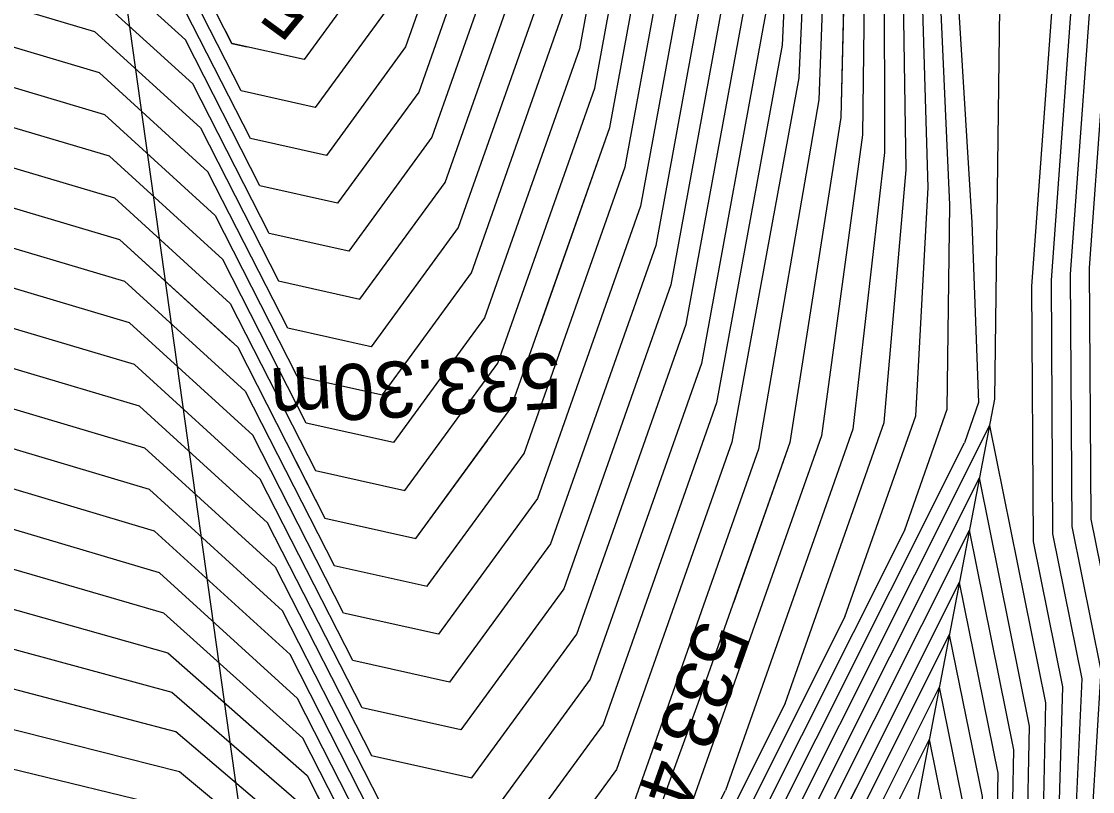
# Model space of a CAD drawing. Extents: x -866683 to -866410, y -1041951 to -1040252.
# Drawn here: x -866454.85 to -866449.11, y -1041936.13 to -1041932.01 of the extents above; entities that cross this region are included whole.
import ezdxf

# ---------------------------------------------------------------- set-up
doc = ezdxf.new("R2010")
doc.units = 0
for name, color, linetype in [('BODY', 7, 'Continuous'), ('BODY_2016', 7, 'Continuous'), ('BREAKLINE', 7, 'Continuous'), ('V-VEDL', 7, 'Continuous'), ('V_po_cm', 7, 'Continuous')]:
    doc.layers.add(name, color=color, linetype=linetype)

msp = doc.modelspace()

# ---------------------------------------------------------------- linework, layer by layer
at = {"layer": 'BREAKLINE'}
for points in [[(-866451.679, -1041950.508), (-866455.618, -1041922.473), (-866456.719, -1041912.396), (-866455.207, -1041909.853), (-866453.752, -1041908.342), (-866450, -1041907.538), (-866447.7, -1041908.076), (-866445.165, -1041909.459), (-866437.422, -1041915.176), (-866426.565, -1041925.108), (-866438.22, -1041915.868), (-866445.312, -1041910.554), (-866447.7, -1041908.076)], [(-866430.202, -1041927.282), (-866445.247, -1041913.64), (-866449.543, -1041926.354), (-866449.641, -1041934.033), (-866450.183, -1041936.864), (-866452.267, -1041937.851), (-866451.576, -1041945.087)]]:
    msp.add_lwpolyline(points, dxfattribs=at)
at = {"layer": 'V-VEDL'}
for points in [[(-866449.6778, -1041924.8534), (-866451.5122, -1041924.6245), (-866452.0867, -1041925.0785), (-866452.3185, -1041926.1012), (-866452.2076, -1041927.6924), (-866452.2736, -1041929.1497), (-866452.5165, -1041930.4732), (-866452.9364, -1041931.6628), (-866453.3395, -1041932.2146), (-866453.7258, -1041932.1285), (-866454.0953, -1041931.4045), (-866454.5968, -1041930.9482), (-866455.2304, -1041930.7597), (-866456.7616, -1041930.9181)], [(-866457.0626, -1041933.1405), (-866455.1284, -1041932.9404), (-866454.3281, -1041933.1785), (-866453.6946, -1041933.7549), (-866453.2278, -1041934.6694), (-866452.7398, -1041934.7782), (-866452.2307, -1041934.0812), (-866451.7003, -1041932.5785), (-866451.3935, -1041930.9067), (-866451.3101, -1041929.0659), (-866451.4503, -1041927.056), (-866451.3268, -1041925.7431), (-866450.9398, -1041925.1272), (-866449.6386, -1041925.2896)], [(-866449.5994, -1041925.7259), (-866450.3673, -1041925.63), (-866450.5669, -1041926.4076), (-866450.582, -1041928.0107), (-866450.4127, -1041930.4394), (-866450.4641, -1041932.5242), (-866450.7364, -1041934.2652), (-866451.2295, -1041935.6623), (-866451.5972, -1041936.6715), (-866451.8395, -1041937.2927), (-866451.9565, -1041937.526), (-866451.8502, -1041937.6044), (-866451.5207, -1041937.5279), (-866450.9679, -1041937.2965), (-866450.586, -1041937.3604), (-866450.3749, -1041937.7197), (-866450.2943, -1041939.0287)], [(-866449.8288, -1041935.014), (-866450.566, -1041936.4847), (-866450.7385, -1041936.9442), (-866450.7148, -1041937.128), (-866450.4951, -1041937.036), (-866450.3432, -1041937.0614), (-866450.2593, -1041937.2042), (-866450.2272, -1041937.7247)], [(-866449.8288, -1041935.014), (-866449.622, -1041936.0349), (-866449.6318, -1041936.5063), (-866449.7548, -1041936.9385), (-866450.2272, -1041937.7247)], [(-866457.3636, -1041935.3629), (-866455.0264, -1041935.1211), (-866454.0691, -1041935.3898), (-866453.3231, -1041936.048), (-866452.7882, -1041937.0959), (-866452.4298, -1041937.7979), (-866452.2476, -1041938.1541), (-866452.2361, -1041938.1747)]]:
    msp.add_lwpolyline(points, dxfattribs=at)
at = {"layer": 'V_po_cm'}
for points in [[(-866448.7617, -1041924.9364), (-866449.2179, -1041924.777), (-866449.4459, -1041924.837), (-866449.8947, -1041924.84), (-866450.5644, -1041924.7859), (-866451.455, -1041924.6747), (-866452.0107, -1041925.145), (-866452.2317, -1041926.1967), (-866452.1179, -1041927.8297), (-866452.1856, -1041929.3254), (-866452.4349, -1041930.6837), (-866452.8658, -1041931.9047), (-866453.2795, -1041932.4709), (-866453.676, -1041932.3826), (-866454.0552, -1041931.6395), (-866454.57, -1041931.1712), (-866455.2202, -1041930.9777)], [(-866448.7851, -1041924.9789), (-866449.2276, -1041924.8242), (-866449.4488, -1041924.8824), (-866449.8842, -1041924.8853), (-866450.5338, -1041924.8328), (-866451.3977, -1041924.725), (-866451.9348, -1041925.2115), (-866452.1449, -1041926.2921), (-866452.0281, -1041927.9671), (-866452.0976, -1041929.5011), (-866452.3533, -1041930.8942), (-866452.7952, -1041932.1465), (-866453.2195, -1041932.7273), (-866453.6262, -1041932.6367), (-866454.0151, -1041931.8745), (-866454.5431, -1041931.3943), (-866455.21, -1041931.1958)], [(-866448.8085, -1041925.0213), (-866449.2373, -1041924.8714), (-866449.4517, -1041924.9279), (-866449.8736, -1041924.9306), (-866450.5033, -1041924.8798), (-866451.3405, -1041924.7753), (-866451.8588, -1041925.2779), (-866452.058, -1041926.3876), (-866451.9384, -1041928.1044), (-866452.0096, -1041929.6768), (-866452.2717, -1041931.1048), (-866452.7247, -1041932.3883), (-866453.1596, -1041932.9837), (-866453.5764, -1041932.8907), (-866453.9751, -1041932.1096), (-866454.5162, -1041931.6173), (-866455.1998, -1041931.4139)], [(-866448.8318, -1041925.0637), (-866449.2471, -1041924.9186), (-866449.4546, -1041924.9733), (-866449.8631, -1041924.976), (-866450.4727, -1041924.9267), (-866451.2833, -1041924.8256), (-866451.7828, -1041925.3444), (-866451.9712, -1041926.4831), (-866451.8486, -1041928.2418), (-866451.9216, -1041929.8525), (-866452.19, -1041931.3153), (-866452.6541, -1041932.6302), (-866453.0996, -1041933.24), (-866453.5266, -1041933.1448), (-866453.935, -1041932.3446), (-866454.4894, -1041931.8403), (-866455.1896, -1041931.632)], [(-866455.1794, -1041931.85), (-866454.4625, -1041932.0634), (-866453.8949, -1041932.5797), (-866453.4768, -1041933.3989), (-866453.0396, -1041933.4964), (-866452.5835, -1041932.872), (-866452.1084, -1041931.5258), (-866451.8335, -1041930.0282), (-866451.7589, -1041928.3791), (-866451.8844, -1041926.5786), (-866451.7068, -1041925.4108), (-866451.226, -1041924.8759), (-866450.4421, -1041924.9737), (-866449.8526, -1041925.0213), (-866449.4575, -1041925.0187), (-866449.2568, -1041924.9659), (-866448.8552, -1041925.1062)], [(-866448.8786, -1041925.1486), (-866449.2665, -1041925.0131), (-866449.4604, -1041925.0641), (-866449.8421, -1041925.0666), (-866450.4115, -1041925.0206), (-866451.1688, -1041924.9261), (-866451.6308, -1041925.4773), (-866451.7976, -1041926.674), (-866451.6691, -1041928.5165), (-866451.7455, -1041930.2039), (-866452.0268, -1041931.7364), (-866452.513, -1041933.1139), (-866452.9797, -1041933.7527), (-866453.427, -1041933.653), (-866453.8549, -1041932.8147), (-866454.4356, -1041932.2864), (-866455.1692, -1041932.0681)], [(-866455.159, -1041932.2862), (-866454.4087, -1041932.5094), (-866453.8148, -1041933.0497), (-866453.3772, -1041933.9071), (-866452.9197, -1041934.0091), (-866452.4424, -1041933.3557), (-866451.9452, -1041931.9469), (-866451.6575, -1041930.3796), (-866451.5794, -1041928.6538), (-866451.7107, -1041926.7695), (-866451.5548, -1041925.5437), (-866451.1115, -1041924.9764), (-866450.3809, -1041925.0676), (-866449.8315, -1041925.112), (-866449.4633, -1041925.1095), (-866449.2763, -1041925.0603), (-866448.902, -1041925.1911)], [(-866448.9254, -1041925.2335), (-866449.286, -1041925.1075), (-866449.4662, -1041925.1549), (-866449.821, -1041925.1573), (-866450.3503, -1041925.1145), (-866451.0543, -1041925.0267), (-866451.4788, -1041925.6102), (-866451.6239, -1041926.865), (-866451.4896, -1041928.7912), (-866451.5695, -1041930.5553), (-866451.8636, -1041932.1574), (-866452.3718, -1041933.5975), (-866452.8598, -1041934.2654), (-866453.3274, -1041934.1612), (-866453.7747, -1041933.2848), (-866454.3819, -1041932.7325), (-866455.1488, -1041932.5042)], [(-866455.1386, -1041932.7223), (-866454.355, -1041932.9555), (-866453.7347, -1041933.5198), (-866453.2776, -1041934.4153), (-866452.7998, -1041934.5218), (-866452.3012, -1041933.8394), (-866451.782, -1041932.368), (-866451.4815, -1041930.731), (-866451.3999, -1041928.9285), (-866451.5371, -1041926.9605), (-866451.4028, -1041925.6766), (-866450.997, -1041925.077), (-866450.3198, -1041925.1615), (-866449.8105, -1041925.2026), (-866449.4691, -1041925.2004), (-866449.2957, -1041925.1547), (-866448.9488, -1041925.276)], [(-866455.1182, -1041933.1585), (-866454.3013, -1041933.4016), (-866453.6545, -1041933.9899), (-866453.178, -1041934.9235), (-866452.6799, -1041935.0345), (-866452.1601, -1041934.323), (-866451.6187, -1041932.789), (-866451.3055, -1041931.0824), (-866451.2204, -1041929.2032), (-866451.3634, -1041927.1514), (-866451.2508, -1041925.8095), (-866450.8825, -1041925.1775), (-866450.2586, -1041925.2554), (-866449.7894, -1041925.2933), (-866449.4749, -1041925.2912), (-866449.3152, -1041925.2491), (-866448.9956, -1041925.3608)], [(-866449.019, -1041925.4033), (-866449.3249, -1041925.2964), (-866449.4778, -1041925.3366), (-866449.7789, -1041925.3386), (-866450.228, -1041925.3023), (-866450.8253, -1041925.2278), (-866451.1748, -1041925.876), (-866451.2766, -1041927.2469), (-866451.1306, -1041929.3406), (-866451.2175, -1041931.2581), (-866451.5371, -1041932.9996), (-866452.0895, -1041934.5649), (-866452.6199, -1041935.2909), (-866453.1282, -1041935.1776), (-866453.6144, -1041934.2249), (-866454.2744, -1041933.6246), (-866455.108, -1041933.3765)], [(-866449.0424, -1041925.4457), (-866449.3347, -1041925.3436), (-866449.4808, -1041925.382), (-866449.7683, -1041925.3839), (-866450.1974, -1041925.3493), (-866450.768, -1041925.2781), (-866451.0988, -1041925.9424), (-866451.1898, -1041927.3424), (-866451.0409, -1041929.4779), (-866451.1295, -1041931.4338), (-866451.4555, -1041933.2101), (-866452.019, -1041934.8067), (-866452.5599, -1041935.5472), (-866453.0784, -1041935.4317), (-866453.5744, -1041934.46), (-866454.2475, -1041933.8476), (-866455.0978, -1041933.5946)], [(-866449.0658, -1041925.4882), (-866449.3444, -1041925.3908), (-866449.4837, -1041925.4275), (-866449.7578, -1041925.4293), (-866450.1669, -1041925.3962), (-866450.7108, -1041925.3283), (-866451.0228, -1041926.0089), (-866451.1029, -1041927.4379), (-866450.9511, -1041929.6153), (-866451.0414, -1041931.6095), (-866451.3739, -1041933.4206), (-866451.9484, -1041935.0486), (-866452.5, -1041935.8036), (-866453.0286, -1041935.6857), (-866453.5343, -1041934.695), (-866454.2206, -1041934.0707), (-866455.0876, -1041933.8127)], [(-866455.0774, -1041934.0307), (-866454.1938, -1041934.2937), (-866453.4942, -1041934.9301), (-866452.9788, -1041935.9398), (-866452.44, -1041936.06), (-866451.8778, -1041935.2904), (-866451.2923, -1041933.6312), (-866450.9534, -1041931.7852), (-866450.8614, -1041929.7526), (-866451.0161, -1041927.5333), (-866450.9468, -1041926.0753), (-866450.6536, -1041925.3786), (-866450.1363, -1041925.4432), (-866449.7473, -1041925.4746), (-866449.4866, -1041925.4729), (-866449.3541, -1041925.438), (-866449.0892, -1041925.5306)], [(-866449.1126, -1041925.5731), (-866449.3639, -1041925.4852), (-866449.4895, -1041925.5183), (-866449.7368, -1041925.5199), (-866450.1057, -1041925.4901), (-866450.5963, -1041925.4289), (-866450.8708, -1041926.1418), (-866450.9293, -1041927.6288), (-866450.7716, -1041929.89), (-866450.8654, -1041931.9609), (-866451.2106, -1041933.8417), (-866451.8073, -1041935.5322), (-866452.3801, -1041936.3163)], [(-866448.7794, -1041925.8129), (-866449.136, -1041925.6155), (-866449.3736, -1041925.5324), (-866449.4924, -1041925.5637), (-866449.7262, -1041925.5653), (-866450.0751, -1041925.5371), (-866450.5391, -1041925.4792), (-866450.7948, -1041926.2083), (-866450.8425, -1041927.7243), (-866450.6819, -1041930.0273), (-866450.7774, -1041932.1366), (-866451.129, -1041934.0522), (-866451.7367, -1041935.7741), (-866452.3201, -1041936.5727)], [(-866448.8233, -1041925.844), (-866449.1594, -1041925.6579), (-866449.3833, -1041925.5797), (-866449.4953, -1041925.6091), (-866449.7157, -1041925.6106), (-866450.0445, -1041925.584), (-866450.4818, -1041925.5295), (-866450.7189, -1041926.2747), (-866450.7556, -1041927.8198), (-866450.5921, -1041930.1647), (-866450.6894, -1041932.3123), (-866451.0474, -1041934.2627), (-866451.6661, -1041936.0159), (-866452.2601, -1041936.829)], [(-866448.8672, -1041925.8751), (-866449.1827, -1041925.7004), (-866449.3931, -1041925.6269), (-866449.4982, -1041925.6546), (-866449.7052, -1041925.6559), (-866450.014, -1041925.631), (-866450.4246, -1041925.5797), (-866450.6429, -1041926.3412), (-866450.6688, -1041927.9153), (-866450.5024, -1041930.302), (-866450.5811, -1041932.4306), (-866450.9049, -1041934.3009), (-866452.0428, -1041937.5251)], [(-866448.955, -1041925.9373), (-866449.2295, -1041925.7853), (-866449.4126, -1041925.7213), (-866449.504, -1041925.7454), (-866449.6841, -1041925.7466), (-866449.9528, -1041925.7249), (-866450.3101, -1041925.6803), (-866450.4909, -1041926.4741), (-866450.4951, -1041928.1062), (-866450.3229, -1041930.5767), (-866450.3472, -1041932.6178), (-866450.5679, -1041934.2295), (-866451.4023, -1041936.5939)], [(-866448.9988, -1041925.9684), (-866449.2529, -1041925.8277), (-866449.4223, -1041925.7685), (-866449.5069, -1041925.7908), (-866449.6736, -1041925.7919), (-866449.9222, -1041925.7718), (-866450.2528, -1041925.7306), (-866450.4149, -1041926.5405), (-866450.4083, -1041928.2017), (-866450.2332, -1041930.7141), (-866450.2302, -1041932.7114), (-866450.3994, -1041934.1937), (-866451.0821, -1041936.1282)], [(-866450.7619, -1041935.6626), (-866450.2308, -1041934.158), (-866450.1132, -1041932.8051), (-866450.1434, -1041930.8514), (-866450.3215, -1041928.2972), (-866450.3389, -1041926.607), (-866450.1956, -1041925.7808), (-866449.8916, -1041925.8188), (-866449.663, -1041925.8372), (-866449.5098, -1041925.8362), (-866449.432, -1041925.8157), (-866449.2763, -1041925.8702), (-866449.0427, -1041925.9995)], [(-866450.4416, -1041935.197), (-866450.0623, -1041934.1223), (-866449.9962, -1041932.8987), (-866450.0537, -1041930.9888), (-866450.2347, -1041928.3927), (-866450.2629, -1041926.6734), (-866450.1383, -1041925.8311), (-866449.861, -1041925.8657), (-866449.6525, -1041925.8826), (-866449.5128, -1041925.8816), (-866449.4418, -1041925.863), (-866449.2997, -1041925.9126), (-866449.0866, -1041926.0306)], [(-866450.1214, -1041934.7314), (-866449.8938, -1041934.0866), (-866449.8792, -1041932.9923), (-866449.9639, -1041931.1261), (-866450.1478, -1041928.4881), (-866450.1869, -1041926.7399), (-866450.0811, -1041925.8814), (-866449.8305, -1041925.9127), (-866449.642, -1041925.9279), (-866449.5157, -1041925.9271), (-866449.4515, -1041925.9102), (-866449.3231, -1041925.955), (-866449.1305, -1041926.0617), (-866448.8737, -1041926.2301)], [(-866448.9449, -1041926.2432), (-866449.1744, -1041926.0928), (-866449.3465, -1041925.9975), (-866449.4612, -1041925.9574), (-866449.5186, -1041925.9725), (-866449.6315, -1041925.9732), (-866449.7999, -1041925.9596), (-866450.0239, -1041925.9317), (-866450.1109, -1041926.8063), (-866450.061, -1041928.5836), (-866449.8742, -1041931.2635), (-866449.7623, -1041933.0859), (-866449.7253, -1041934.0509), (-866449.8011, -1041934.2658)], [(-866448.9066, -1041928.9254), (-866449.1964, -1041931.4523), (-866449.3373, -1041933.3952), (-866449.3293, -1041934.7542), (-866449.1723, -1041935.5291), (-866449.206, -1041936.276), (-866449.4305, -1041936.9949), (-866449.8456, -1041937.6858), (-866450.1318, -1041937.9939), (-866450.2889, -1041937.9193), (-866450.3171, -1041937.4619), (-866450.4646, -1041937.2109), (-866450.7315, -1041937.1663), (-866451.504, -1041937.4896)], [(-866451.3901, -1041937.4357), (-866450.6842, -1041937.1402), (-866450.4403, -1041937.181), (-866450.3055, -1041937.4104), (-866450.2798, -1041937.8283), (-866450.1362, -1041937.8965), (-866449.8747, -1041937.615), (-866449.4954, -1041936.9836), (-866449.2951, -1041936.3031), (-866449.2738, -1041935.5732), (-866449.4316, -1041934.7942), (-866449.4397, -1041933.428), (-866449.2981, -1041931.4746), (-866449.0067, -1041928.9342)], [(-866452.0741, -1041933.6376), (-866451.7003, -1041932.5785), (-866451.3935, -1041930.9067), (-866451.3487, -1041929.9179)], [(-866450.4275, -1041931.0422), (-866450.4641, -1041932.5242), (-866450.7364, -1041934.2652), (-866451.0388, -1041935.1221)], [(-866448.9932, -1041931.4077), (-866449.1325, -1041933.3298), (-866449.1246, -1041934.6742), (-866448.9693, -1041935.4409)], [(-866449.0948, -1041931.43), (-866449.2349, -1041933.3625), (-866449.2269, -1041934.7142), (-866449.0708, -1041935.485), (-866449.117, -1041936.249), (-866449.3656, -1041937.0062), (-866449.8165, -1041937.7566), (-866450.1274, -1041938.0913), (-866450.2981, -1041938.0103), (-866450.3286, -1041937.5135), (-866450.4889, -1041937.2408), (-866450.7788, -1041937.1923), (-866451.6179, -1041937.5436)], [(-866453.7594, -1041932.0625), (-866453.7258, -1041932.1285), (-866453.6449, -1041932.1465)], [(-866457.2504, -1041933.1634), (-866457.1187, -1041933.1491), (-866456.0955, -1041933.0404), (-866455.1284, -1041932.9404), (-866454.3281, -1041933.1785), (-866453.7229, -1041933.7291)], [(-866449.6678, -1041934.1731), (-866451.2762, -1041937.3818)], [(-866449.6678, -1041934.1731), (-866449.3671, -1041935.6581), (-866449.3813, -1041936.3437), (-866449.5602, -1041936.9724), (-866449.9038, -1041937.5441), (-866450.1406, -1041937.7991), (-866450.2707, -1041937.7374), (-866450.294, -1041937.3588), (-866450.4161, -1041937.1511), (-866450.6369, -1041937.1141), (-866451.2762, -1041937.3818)], [(-866452.929, -1041936.1939), (-866453.4542, -1041935.1651), (-866454.1669, -1041934.5167), (-866455.0672, -1041934.2488), (-866456.1552, -1041934.3614), (-866457.2188, -1041934.4739), (-866458.2579, -1041934.5864), (-866459.2726, -1041934.699), (-866459.9913, -1041934.8108), (-866460.414, -1041934.9221), (-866460.5406, -1041935.0327), (-866460.6694, -1041935.1033), (-866460.8005, -1041935.1338), (-866461.067, -1041935.1147)], [(-866453.4099, -1041934.3126), (-866453.2278, -1041934.6694), (-866452.7398, -1041934.7782), (-866452.3571, -1041934.2542)], [(-866451.3901, -1041937.4357), (-866449.8011, -1041934.2658)], [(-866451.1624, -1041937.3278), (-866449.7215, -1041934.4534)], [(-866451.1624, -1041937.3278), (-866450.5896, -1041937.0881), (-866450.3918, -1041937.1212), (-866450.2824, -1041937.3073), (-866450.2615, -1041937.6464), (-866450.145, -1041937.7017), (-866449.9329, -1041937.4733), (-866449.6251, -1041936.9611), (-866449.4648, -1041936.3979), (-866449.452, -1041935.7837), (-866449.7215, -1041934.4534)], [(-866452.8792, -1041936.448), (-866453.4141, -1041935.4001), (-866454.14, -1041934.7397), (-866455.057, -1041934.4669), (-866456.1652, -1041934.5815), (-866457.2354, -1041934.6947), (-866458.2679, -1041934.8065), (-866459.2625, -1041934.9167), (-866459.967, -1041935.0264), (-866460.3813, -1041935.1355), (-866460.5054, -1041935.2439), (-866460.6317, -1041935.313), (-866460.7601, -1041935.3429), (-866461.0214, -1041935.3242)], [(-866452.8294, -1041936.7021), (-866453.374, -1041935.6352), (-866454.1131, -1041934.9628), (-866455.0468, -1041934.6849), (-866456.1751, -1041934.8017), (-866457.2521, -1041934.9155), (-866458.2779, -1041935.0265), (-866459.2524, -1041935.1345), (-866459.9427, -1041935.242), (-866460.3486, -1041935.3488), (-866460.4702, -1041935.4551), (-866460.5939, -1041935.5228), (-866460.7198, -1041935.5521), (-866460.9758, -1041935.5338)], [(-866450.1214, -1041934.7314), (-866451.504, -1041937.4896)], [(-866451.0485, -1041937.2739), (-866449.7752, -1041934.7337)], [(-866451.0485, -1041937.2739), (-866450.5424, -1041937.062), (-866450.3675, -1041937.0913), (-866450.2709, -1041937.2557), (-866450.2524, -1041937.5554), (-866450.1494, -1041937.6043), (-866449.962, -1041937.4024), (-866449.69, -1041936.9498), (-866449.5483, -1041936.4521), (-866449.537, -1041935.9093), (-866449.7752, -1041934.7337)], [(-866452.2614, -1041937.9715), (-866453.346, -1041935.8467), (-866454.0903, -1041935.178), (-866455.0366, -1041934.903), (-866456.185, -1041935.0218), (-866457.2688, -1041935.1363), (-866458.2879, -1041935.2465), (-866459.2423, -1041935.3523), (-866459.9183, -1041935.4575), (-866460.3159, -1041935.5622), (-866460.435, -1041935.6662), (-866460.5562, -1041935.7326), (-866460.6795, -1041935.7613), (-866460.9301, -1041935.7433)], [(-866449.8288, -1041935.014), (-866450.9346, -1041937.22)], [(-866449.8288, -1041935.014), (-866449.622, -1041936.0349), (-866449.6318, -1041936.5063), (-866449.7548, -1041936.9385), (-866449.991, -1041937.3316), (-866450.1539, -1041937.5069), (-866450.2433, -1041937.4644), (-866450.2593, -1041937.2042), (-866450.3432, -1041937.0614), (-866450.4951, -1041937.036), (-866450.9346, -1041937.22)], [(-866456.7789, -1041935.3036), (-866456.195, -1041935.242), (-866455.0264, -1041935.1211), (-866454.0691, -1041935.3898), (-866453.3231, -1041936.048), (-866453.1636, -1041936.3606)], [(-866450.4416, -1041935.197), (-866451.6179, -1041937.5436)], [(-866449.8825, -1041935.2943), (-866450.8207, -1041937.166)], [(-866449.8825, -1041935.2943), (-866449.707, -1041936.1606), (-866449.7154, -1041936.5605), (-866449.8197, -1041936.9272), (-866450.0201, -1041937.2607), (-866450.1583, -1041937.4095), (-866450.2341, -1041937.3735), (-866450.2477, -1041937.1527), (-866450.319, -1041937.0315), (-866450.4478, -1041937.0099), (-866450.8207, -1041937.166)], [(-866460.8389, -1041936.1624), (-866460.5988, -1041936.1796), (-866460.4807, -1041936.1521), (-866460.3646, -1041936.0886), (-866460.2505, -1041935.9889), (-866459.8697, -1041935.8887), (-866459.2222, -1041935.7879), (-866458.3079, -1041935.6865), (-866457.3022, -1041935.5779), (-866456.2049, -1041935.4621), (-866455.0162, -1041935.3392), (-866454.048, -1041935.6016), (-866453.3002, -1041936.2494), (-866452.2454, -1041938.316)], [(-866452.2374, -1041938.4882), (-866453.2773, -1041936.4508), (-866454.0268, -1041935.8134), (-866455.006, -1041935.5572), (-866456.2149, -1041935.6823), (-866457.3188, -1041935.7987), (-866458.3179, -1041935.9065), (-866459.2121, -1041936.0057), (-866459.8454, -1041936.1043), (-866460.2178, -1041936.2023), (-866460.3294, -1041936.2997), (-866460.4429, -1041936.3619), (-866460.5584, -1041936.3888), (-866460.7933, -1041936.372)], [(-866449.9361, -1041935.5746), (-866450.7068, -1041937.1121)], [(-866449.9361, -1041935.5746), (-866449.792, -1041936.2862), (-866449.7989, -1041936.6147), (-866449.8846, -1041936.9159), (-866450.0492, -1041937.1899), (-866450.1627, -1041937.3121), (-866450.225, -1041937.2825), (-866450.2362, -1041937.1011), (-866450.2947, -1041937.0016), (-866450.4005, -1041936.9839), (-866450.7068, -1041937.1121)], [(-866450.7619, -1041935.6626), (-866451.7318, -1041937.5975)], [(-866460.7476, -1041936.5815), (-866460.5181, -1041936.598), (-866460.4052, -1041936.5717), (-866460.2942, -1041936.5109), (-866460.1851, -1041936.4156), (-866459.821, -1041936.3198), (-866459.202, -1041936.2234), (-866458.3279, -1041936.1265), (-866457.3355, -1041936.0195), (-866456.2248, -1041935.9024), (-866454.9958, -1041935.7753), (-866454.0057, -1041936.0252), (-866453.2544, -1041936.6522), (-866452.2294, -1041938.6604)], [(-866449.9898, -1041935.8549), (-866450.593, -1041937.0582)], [(-866449.9898, -1041935.8549), (-866449.877, -1041936.4118), (-866449.8824, -1041936.6689), (-866449.9495, -1041936.9046), (-866450.0783, -1041937.119), (-866450.1671, -1041937.2147), (-866450.2159, -1041937.1915), (-866450.2246, -1041937.0496), (-866450.2704, -1041936.9717), (-866450.3532, -1041936.9578), (-866450.593, -1041937.0582)], [(-866452.2214, -1041938.8326), (-866453.2315, -1041936.8536), (-866453.9845, -1041936.237), (-866454.9856, -1041935.9934), (-866456.2348, -1041936.1226), (-866457.3522, -1041936.2403), (-866458.3379, -1041936.3465), (-866459.1919, -1041936.4412), (-866459.7967, -1041936.5354), (-866460.1524, -1041936.629), (-866460.259, -1041936.7221), (-866460.3674, -1041936.7815), (-866460.4777, -1041936.8072), (-866460.702, -1041936.7911)], [(-866451.8456, -1041937.6514), (-866451.0821, -1041936.1282)]]:
    msp.add_lwpolyline(points, dxfattribs=at)

# ---------------------------------------------------------------- texts
at = {"layer": 'BODY'}
msp.add_text('+', height=0.001, rotation=360, dxfattribs=at).set_placement((-866449.641, -1041934.033))
at = {"layer": 'BODY_2016'}
msp.add_text('+', height=0.001, rotation=360, dxfattribs=at).set_placement((-866449.641, -1041934.033))
at = {"layer": 'V_po_cm'}
for s, rotation, p in [('533.20m', 143.74614, (-866453.2373, -1041931.8874)), ('533.30m', 183.17545, (-866451.9694, -1041933.782)), ('533.40m', 250.56087, (-866451.2252, -1041935.1995))]:
    msp.add_text(s, height=0.3, rotation=rotation, dxfattribs=at).set_placement(p)

doc.saveas('drawing.dxf')
